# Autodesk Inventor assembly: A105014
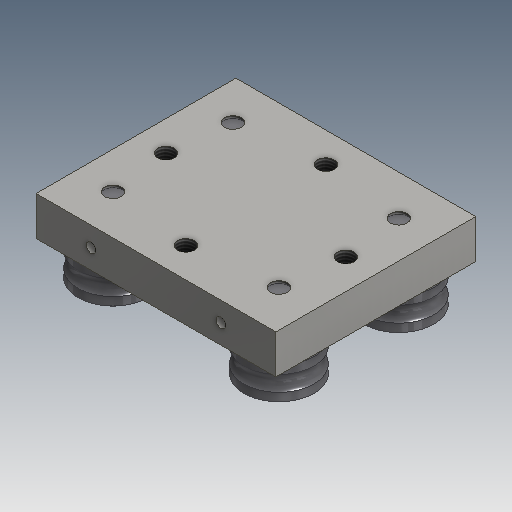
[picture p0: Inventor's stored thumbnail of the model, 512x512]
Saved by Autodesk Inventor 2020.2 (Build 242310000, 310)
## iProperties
Created: 1999-12
Part Number: A105014
Document SubType Name: Assembly
Designer: tgregory
Mass: 1148.83 g
Surface Area: 614.118 cm^2
Volume: 293.554 cm^3
Density: 3.91352 g/cm^3
Control State: 0
Checked Out: False
Last Check In By: gpurviance
Last Check In Date: 2000-01-06
Master: False
Shininess: 0.0
Length Units: 11269
Angle Units: 11279
Time Units: 11290
Mass Units: 11283
Length Display Precision: 3
Angle Display Precision: 2
Compacted: True
Dimensions: 44,2x106,4x133 mm
Mass: 1,149 kg
DocNumber: A105014.iam
Folder: 01 - Themengebiete\Simplification\01 - Packaging machine\
VDS_Category: 3D Komponenten
Density: 0.0
Volumn: 0.0
Area: 0.0
PropertySet Name: Model Information
Author: tgregory
Revision Number: -
Title: carriage
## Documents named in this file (4)
- D:\07 - DEMODATEN\OTX 2019 - Dataset - UPDATE - Dez2019\Designs\07-Packing machine\A105014.iam
- D:\07 - DEMODATEN\OTX 2019 - Dataset - UPDATE - Dez2019\Designs\07-Packing machine\Parts\ADSK-011783.ipt
- D:\07 - DEMODATEN\OTX 2019 - Dataset - UPDATE - Dez2019\Designs\07-Packing machine\Parts\ADSK-011782.ipt
- D:\07 - DEMODATEN\OTX 2019 - Dataset - UPDATE - Dez2019\Designs\07-Packing machine\Parts\ADSK-011784.ipt
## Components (9 placed, 3 different names)
1. ADSK-011782:1 — Mate:1, Mate:2, Mate:3, Mate:4, Mate:5, Mate:6, Mate:7, Mate:8
2. ADSK-011783:1 — Mate:1, Mate:2, Mate:15, Mate:16
3. ADSK-011783:2 — Mate:3, Mate:4, Mate:13, Mate:14
4. ADSK-011783:3 — Mate:5, Mate:8, Mate:9, Mate:10
5. ADSK-011783:4 — Mate:6, Mate:7, Mate:11, Mate:12
6. ADSK-011784:1 — Mate:13, Mate:14
7. ADSK-011784:2 — Mate:11, Mate:12
8. ADSK-011784:3 — Mate:15, Mate:16
9. ADSK-011784:4 — Mate:9, Mate:10
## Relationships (16: Mate 16)
- Mate:1: ADSK-011782:1 ↔ ADSK-011783:1
- Mate:2: ADSK-011782:1 ↔ ADSK-011783:1
- Mate:3: ADSK-011782:1 ↔ ADSK-011783:2
- Mate:4: ADSK-011782:1 ↔ ADSK-011783:2
- Mate:5: ADSK-011782:1 ↔ ADSK-011783:3
- Mate:6: ADSK-011782:1 ↔ ADSK-011783:4
- Mate:7: ADSK-011782:1 ↔ ADSK-011783:4
- Mate:8: ADSK-011782:1 ↔ ADSK-011783:3
- Mate:9: ADSK-011783:3 ↔ ADSK-011784:4
- Mate:10: ADSK-011783:3 ↔ ADSK-011784:4
- Mate:11: ADSK-011783:4 ↔ ADSK-011784:2
- Mate:12: ADSK-011783:4 ↔ ADSK-011784:2
- Mate:13: ADSK-011783:2 ↔ ADSK-011784:1
- Mate:14: ADSK-011783:2 ↔ ADSK-011784:1
- Mate:15: ADSK-011783:1 ↔ ADSK-011784:3
- Mate:16: ADSK-011783:1 ↔ ADSK-011784:3
